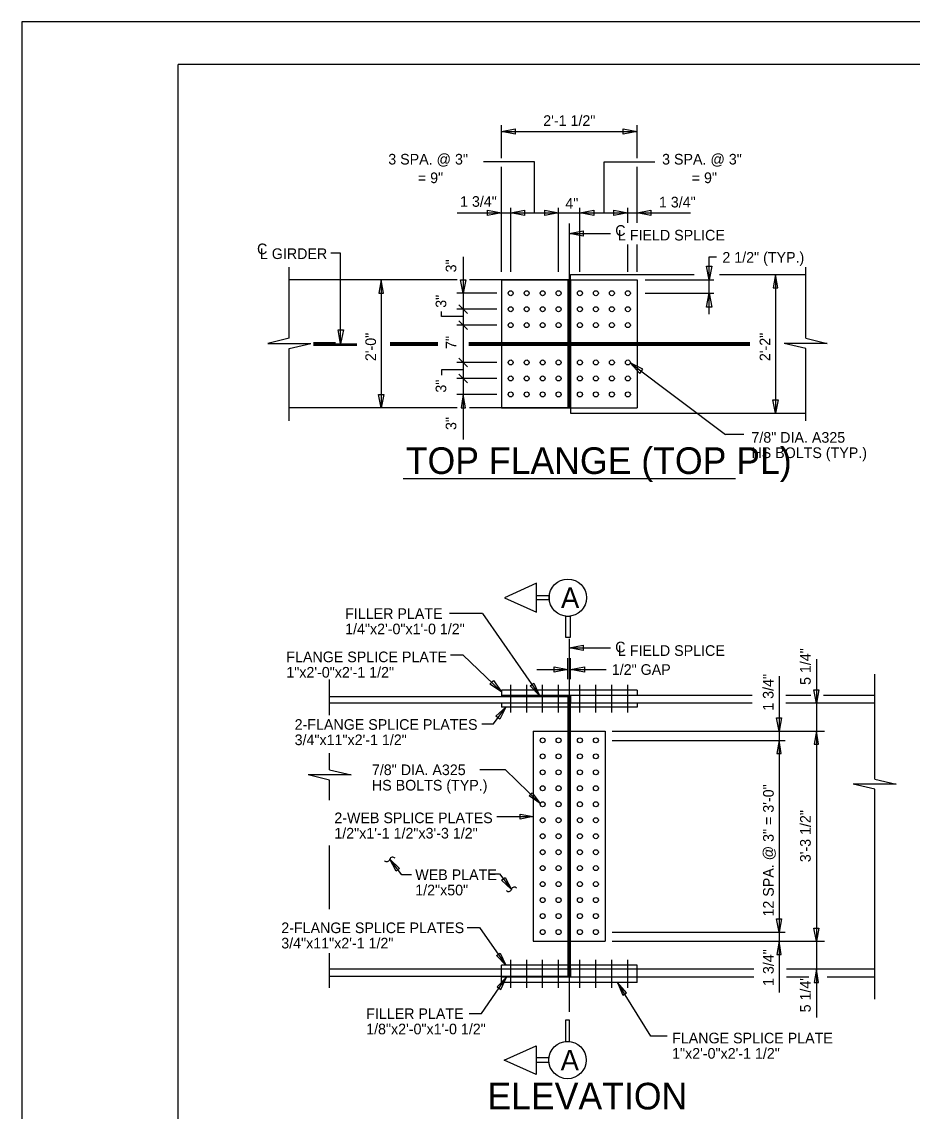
# Model space of a CAD drawing. Extents: x -448.1 to -400, y -140.7 to -111.4.
# Drawn here: x -448.13 to -434.2, y -128.41 to -111.36 of the extents above; entities that cross this region are included whole.
import ezdxf

# ---------------------------------------------------------------- set-up
doc = ezdxf.new("R2010")
doc.units = 0
for name, color, linetype in [('BR_AUTO DIMENSION', 7, 'Continuous'), ('BR_BORDER LINES', 7, 'Continuous'), ('BR_CENTER LINES', 7, 'Continuous'), ('BR_STRUCTURAL STEEL', 7, 'Continuous'), ('BR_TEXT', 7, 'Continuous'), ('Default', 7, 'Continuous'), ('Level 31', 7, 'Continuous')]:
    doc.layers.add(name, color=color, linetype=linetype)

msp = doc.modelspace()

# ---------------------------------------------------------------- linework, layer by layer
at = {"layer": 'BR_AUTO DIMENSION'}
for p, q in [((-440.631, -113.5), (-440.631, -112.984)), ((-438.506, -113.5), (-438.506, -112.984)), ((-440.631, -113.083), (-438.506, -113.083)), ((-440.631, -115.277), (-440.631, -113.636)), ((-438.506, -114.509), (-438.506, -113.636)), ((-441.321, -114.353), (-437.67, -114.353)), ((-440.485, -115.277), (-440.485, -114.278)), ((-439.735, -115.277), (-439.735, -114.278)), ((-439.402, -115.277), (-439.402, -114.278)), ((-438.652, -114.509), (-438.652, -114.278)), ((-438.652, -115.277), (-438.652, -114.85)), ((-438.506, -115.277), (-438.506, -114.85)), ((-443.145, -114.986), (-443.299, -114.986)), ((-443.145, -116.404), (-443.145, -114.986)), ((-441.228, -115.044), (-441.228, -117.899)), ((-437.38, -115.938), (-437.38, -115.042)), ((-437.38, -115.042), (-437.263, -115.042)), ((-442.511, -115.404), (-442.511, -117.404)), ((-438.382, -115.404), (-437.305, -115.404)), ((-436.343, -115.321), (-436.343, -117.487)), ((-440.704, -115.612), (-441.329, -115.612)), ((-438.382, -115.612), (-437.305, -115.612)), ((-440.704, -115.862), (-441.329, -115.862)), ((-441.161, -115.93), (-441.294, -115.795)), ((-441.161, -116.18), (-441.294, -116.045)), ((-440.704, -116.112), (-441.329, -116.112)), ((-440.704, -116.696), (-441.329, -116.696)), ((-441.161, -116.763), (-441.294, -116.628)), ((-438.614, -116.704), (-437.124, -117.825)), ((-440.704, -116.946), (-441.329, -116.946)), ((-441.161, -117.013), (-441.294, -116.878)), ((-440.704, -117.196), (-441.329, -117.196)), ((-436.838, -117.825), (-437.124, -117.825)), ((-440.926, -120.623), (-441.443, -120.623)), ((-440.926, -120.623), (-440.033, -121.906)), ((-441.428, -121.27), (-441.234, -121.27)), ((-441.234, -121.27), (-440.631, -121.848)), ((-439.59, -121.65), (-439.59, -121.323)), ((-439.548, -121.65), (-439.548, -121.323)), ((-435.703, -121.337), (-435.703, -126.945)), ((-435.703, -121.36), (-435.703, -122.255)), ((-440.076, -121.501), (-439.59, -121.501)), ((-439.548, -121.501), (-438.993, -121.501)), ((-436.286, -121.603), (-436.286, -126.554)), ((-440.756, -122.349), (-440.562, -122.089)), ((-440.939, -122.349), (-440.756, -122.349)), ((-438.9, -122.464), (-435.576, -122.464)), ((-438.9, -122.61), (-436.189, -122.61)), ((-440.969, -123.068), (-440.573, -123.068)), ((-440.023, -123.598), (-440.573, -123.068)), ((-440.702, -123.803), (-440.131, -123.803)), ((-442.19, -124.714), (-442.377, -124.472)), ((-442.036, -124.714), (-442.19, -124.714)), ((-440.814, -124.7), (-440.661, -124.7)), ((-440.661, -124.7), (-440.473, -124.942)), ((-441.165, -125.537), (-440.971, -125.537)), ((-440.971, -125.537), (-440.559, -126.13)), ((-438.9, -125.61), (-436.189, -125.61)), ((-438.9, -125.755), (-435.576, -125.755)), ((-440.942, -126.885), (-440.548, -126.318)), ((-438.295, -127.238), (-438.813, -126.401)), ((-441.136, -126.885), (-440.942, -126.885)), ((-438.038, -127.238), (-438.295, -127.238))]:
    msp.add_line(p, q, dxfattribs=at)
for points in [[(-440.415, -113.125), (-440.631, -113.083), (-440.415, -113.042)], [(-438.723, -113.042), (-438.506, -113.083), (-438.723, -113.125)], [(-440.848, -114.312), (-440.631, -114.353), (-440.848, -114.395)], [(-440.269, -114.395), (-440.485, -114.353), (-440.269, -114.312)], [(-439.952, -114.312), (-439.735, -114.353), (-439.952, -114.395)], [(-439.185, -114.395), (-439.402, -114.353), (-439.185, -114.312)], [(-438.869, -114.312), (-438.652, -114.353), (-438.869, -114.395)], [(-438.29, -114.395), (-438.506, -114.353), (-438.29, -114.312)], [(-439.352, -114.717), (-439.569, -114.676), (-439.352, -114.634)], [(-437.338, -115.187), (-437.38, -115.404), (-437.421, -115.187)], [(-442.546, -115.612), (-442.476, -115.612), (-442.511, -115.404)], [(-441.188, -115.404), (-441.228, -115.612), (-441.268, -115.404)], [(-436.378, -115.529), (-436.308, -115.529), (-436.343, -115.321)], [(-437.421, -115.829), (-437.38, -115.612), (-437.338, -115.829)], [(-443.103, -116.187), (-443.145, -116.404), (-443.186, -116.187)], [(-438.416, -116.801), (-438.614, -116.704), (-438.466, -116.868)], [(-442.471, -117.196), (-442.511, -117.404), (-442.551, -117.196)], [(-441.262, -117.404), (-441.193, -117.404), (-441.228, -117.196)], [(-436.303, -117.279), (-436.343, -117.487), (-436.383, -117.279)], [(-439.352, -121.203), (-439.569, -121.161), (-439.352, -121.119)], [(-439.806, -121.459), (-439.59, -121.501), (-439.806, -121.543)], [(-439.331, -121.543), (-439.548, -121.501), (-439.331, -121.459)], [(-440.754, -121.675), (-440.631, -121.848), (-440.809, -121.733)], [(-440.181, -121.755), (-440.124, -121.716), (-440.033, -121.906)], [(-435.663, -121.818), (-435.703, -122.026), (-435.743, -121.818)], [(-440.719, -122.232), (-440.562, -122.089), (-440.655, -122.279)], [(-436.246, -122.256), (-436.286, -122.464), (-436.326, -122.256)], [(-435.738, -122.672), (-435.668, -122.672), (-435.703, -122.464)], [(-436.321, -122.818), (-436.251, -122.818), (-436.286, -122.61)], [(-440.197, -123.479), (-440.149, -123.429), (-440.023, -123.598)], [(-440.339, -123.763), (-440.131, -123.803), (-440.339, -123.843)], [(-442.222, -124.616), (-442.277, -124.658), (-442.377, -124.472)], [(-440.629, -124.798), (-440.574, -124.756), (-440.473, -124.942)], [(-436.246, -125.402), (-436.286, -125.61), (-436.326, -125.402)], [(-435.663, -125.547), (-435.703, -125.755), (-435.743, -125.547)], [(-436.321, -125.964), (-436.251, -125.964), (-436.286, -125.755)], [(-440.706, -125.979), (-440.649, -125.94), (-440.559, -126.13)], [(-440.695, -126.469), (-440.638, -126.509), (-440.548, -126.318)], [(-435.738, -126.401), (-435.668, -126.401), (-435.703, -126.193)], [(-438.733, -126.597), (-438.674, -126.56), (-438.813, -126.401)]]:
    msp.add_lwpolyline(points, close=True, dxfattribs=at)
for points in [[(-440.113, -114.353), (-440.113, -113.557), (-440.91, -113.557)], [(-440.113, -114.353), (-440.113, -113.557), (-440.91, -113.557)], [(-439.024, -114.353), (-439.024, -113.557), (-438.228, -113.557)], [(-439.569, -114.676), (-438.921, -114.676)], [(-441.228, -115.979), (-441.565, -115.979), (-441.565, -115.897)], [(-441.228, -116.812), (-441.565, -116.812), (-441.565, -116.894)], [(-439.569, -121.161), (-438.921, -121.161)]]:
    msp.add_lwpolyline(points, dxfattribs=at)
at = {"layer": 'BR_BORDER LINES'}
for p in [(-400.801, -112.031), (-445.689, -140.031)]:
    msp.add_line(p, (-445.689, -112.031), dxfattribs=at)
at = {"layer": 'BR_CENTER LINES'}
for p, q in [((-439.569, -114.519), (-439.569, -117.404)), ((-443.568, -116.404), (-442.892, -116.404)), ((-442.371, -116.404), (-441.627, -116.404)), ((-441.142, -116.404), (-436.742, -116.404)), ((-439.569, -121.021), (-439.569, -126.859))]:
    msp.add_line(p, q, dxfattribs=at)
at = {"layer": 'BR_STRUCTURAL STEEL'}
for p, q in [((-441.323, -115.404), (-443.95, -115.404)), ((-439.548, -115.404), (-441.132, -115.404)), ((-440.631, -115.404), (-438.506, -115.404)), ((-440.631, -115.404), (-440.631, -117.404)), ((-439.59, -115.404), (-439.59, -117.404)), ((-439.548, -115.404), (-439.548, -115.321)), ((-439.548, -115.321), (-437.614, -115.321)), ((-439.548, -115.404), (-439.548, -117.404)), ((-438.506, -115.404), (-438.506, -117.404)), ((-437.22, -115.321), (-435.869, -115.321)), ((-443.568, -116.383), (-443.227, -116.383)), ((-443.568, -116.425), (-442.892, -116.425)), ((-442.371, -116.383), (-441.627, -116.383)), ((-442.371, -116.425), (-441.627, -116.425)), ((-441.142, -116.383), (-439.59, -116.383)), ((-441.142, -116.425), (-439.59, -116.425)), ((-439.548, -116.383), (-436.742, -116.383)), ((-439.548, -116.425), (-436.742, -116.425)), ((-441.323, -117.404), (-443.95, -117.404)), ((-439.59, -117.404), (-441.132, -117.404)), ((-440.631, -117.404), (-438.506, -117.404)), ((-439.548, -117.404), (-439.548, -117.487)), ((-439.548, -117.487), (-435.869, -117.487)), ((-440.631, -121.823), (-440.631, -121.906)), ((-438.506, -121.823), (-440.631, -121.823)), ((-440.485, -122.172), (-440.485, -121.74)), ((-440.485, -122.089), (-440.485, -121.823)), ((-440.235, -122.172), (-440.235, -121.74)), ((-439.985, -122.172), (-439.985, -121.74)), ((-439.735, -122.172), (-439.735, -121.74)), ((-439.402, -122.172), (-439.402, -121.74)), ((-439.152, -122.172), (-439.152, -121.74)), ((-438.902, -122.172), (-438.902, -121.74)), ((-438.652, -122.172), (-438.652, -121.74)), ((-438.506, -121.823), (-438.506, -121.906)), ((-439.59, -121.927), (-443.319, -121.927)), ((-436.708, -122.026), (-443.319, -122.026)), ((-440.631, -121.906), (-440.631, -121.927)), ((-438.506, -121.906), (-440.631, -121.906)), ((-440.631, -122.026), (-440.631, -122.089)), ((-438.944, -121.906), (-440.194, -121.906)), ((-439.59, -121.906), (-439.59, -121.927)), ((-439.59, -121.906), (-439.59, -122.026)), ((-439.59, -122.026), (-439.59, -126.193)), ((-439.548, -121.906), (-439.548, -122.026)), ((-436.708, -121.906), (-439.548, -121.906)), ((-439.548, -126.193), (-439.548, -122.026)), ((-438.506, -122.026), (-438.506, -122.089)), ((-435.79, -121.906), (-436.179, -121.906)), ((-434.789, -122.026), (-436.179, -122.026)), ((-434.789, -121.906), (-435.591, -121.906)), ((-438.506, -122.089), (-440.631, -122.089)), ((-440.131, -122.464), (-440.131, -125.755)), ((-440.131, -122.464), (-439.006, -122.464)), ((-439.006, -122.464), (-439.006, -125.755)), ((-440.131, -125.755), (-439.006, -125.755)), ((-440.631, -126.401), (-440.631, -126.13)), ((-438.506, -126.13), (-440.631, -126.13)), ((-440.485, -126.485), (-440.485, -126.047)), ((-440.235, -126.485), (-440.235, -126.047)), ((-439.985, -126.485), (-439.985, -126.047)), ((-439.735, -126.485), (-439.735, -126.047)), ((-439.402, -126.485), (-439.402, -126.047)), ((-439.152, -126.485), (-439.152, -126.047)), ((-438.902, -126.485), (-438.902, -126.047)), ((-438.652, -126.485), (-438.652, -126.047)), ((-438.506, -126.401), (-438.506, -126.13)), ((-436.682, -126.193), (-443.319, -126.193)), ((-439.59, -126.308), (-443.319, -126.308)), ((-438.506, -126.318), (-440.631, -126.318)), ((-439.59, -126.193), (-439.59, -126.318)), ((-439.548, -126.193), (-439.548, -126.318)), ((-436.682, -126.318), (-439.548, -126.318)), ((-434.789, -126.193), (-436.17, -126.193)), ((-435.823, -126.318), (-436.17, -126.318)), ((-434.789, -126.318), (-435.535, -126.318)), ((-438.506, -126.401), (-440.631, -126.401))]:
    msp.add_line(p, q, dxfattribs=at)
for centre in [(-440.485, -115.612), (-440.485, -115.612), (-440.235, -115.612), (-440.235, -115.612), (-439.985, -115.612), (-439.985, -115.612), (-439.735, -115.612), (-439.735, -115.612), (-439.402, -115.612), (-439.402, -115.612), (-439.152, -115.612), (-439.152, -115.612), (-438.902, -115.612), (-438.902, -115.612), (-438.652, -115.612), (-438.652, -115.612), (-440.485, -115.862), (-440.485, -115.862), (-440.235, -115.862), (-440.235, -115.862), (-439.985, -115.862), (-439.985, -115.862), (-439.735, -115.862), (-439.735, -115.862), (-439.402, -115.862), (-439.402, -115.862), (-439.152, -115.862), (-439.152, -115.862), (-438.902, -115.862), (-438.902, -115.862), (-438.652, -115.862), (-438.652, -115.862), (-440.485, -116.112), (-440.485, -116.112), (-440.235, -116.112), (-440.235, -116.112), (-439.985, -116.112), (-439.985, -116.112), (-439.735, -116.112), (-439.735, -116.112), (-439.402, -116.112), (-439.402, -116.112), (-439.152, -116.112), (-439.152, -116.112), (-438.902, -116.112), (-438.902, -116.112), (-438.652, -116.112), (-438.652, -116.112), (-440.485, -116.696), (-440.485, -116.696), (-440.235, -116.696), (-440.235, -116.696), (-439.985, -116.696), (-439.985, -116.696), (-439.735, -116.696), (-439.735, -116.696), (-439.402, -116.696), (-439.402, -116.696), (-439.152, -116.696), (-439.152, -116.696), (-438.902, -116.696), (-438.902, -116.696), (-438.652, -116.696), (-438.652, -116.696), (-440.485, -116.946), (-440.485, -116.946), (-440.235, -116.946), (-440.235, -116.946), (-439.985, -116.946), (-439.985, -116.946), (-439.735, -116.946), (-439.735, -116.946), (-439.402, -116.946), (-439.402, -116.946), (-439.152, -116.946), (-439.152, -116.946), (-438.902, -116.946), (-438.902, -116.946), (-438.652, -116.946), (-438.652, -116.946), (-440.485, -117.196), (-440.485, -117.196), (-440.235, -117.196), (-440.235, -117.196), (-439.985, -117.196), (-439.985, -117.196), (-439.735, -117.196), (-439.735, -117.196), (-439.402, -117.196), (-439.402, -117.196), (-439.152, -117.196), (-439.152, -117.196), (-438.902, -117.196), (-438.902, -117.196), (-438.652, -117.196), (-438.652, -117.196), (-439.985, -122.61), (-439.985, -122.61), (-439.735, -122.61), (-439.735, -122.61), (-439.402, -122.61), (-439.402, -122.61), (-439.152, -122.61), (-439.152, -122.61), (-439.985, -122.86), (-439.985, -122.86), (-439.735, -122.86), (-439.735, -122.86), (-439.402, -122.86), (-439.402, -122.86), (-439.152, -122.86), (-439.152, -122.86), (-439.985, -123.11), (-439.985, -123.11), (-439.735, -123.11), (-439.735, -123.11), (-439.402, -123.11), (-439.402, -123.11), (-439.152, -123.11), (-439.152, -123.11), (-439.985, -123.36), (-439.985, -123.36), (-439.735, -123.36), (-439.735, -123.36), (-439.402, -123.36), (-439.402, -123.36), (-439.152, -123.36), (-439.152, -123.36), (-439.985, -123.61), (-439.985, -123.61), (-439.735, -123.61), (-439.735, -123.61), (-439.402, -123.61), (-439.402, -123.61), (-439.152, -123.61), (-439.152, -123.61), (-439.985, -123.86), (-439.985, -123.86), (-439.735, -123.86), (-439.735, -123.86), (-439.402, -123.86), (-439.402, -123.86), (-439.152, -123.86), (-439.152, -123.86), (-439.985, -124.11), (-439.985, -124.11), (-439.735, -124.11), (-439.735, -124.11), (-439.402, -124.11), (-439.402, -124.11), (-439.152, -124.11), (-439.152, -124.11), (-439.985, -124.36), (-439.985, -124.36), (-439.735, -124.36), (-439.735, -124.36), (-439.402, -124.36), (-439.402, -124.36), (-439.152, -124.36), (-439.152, -124.36), (-439.985, -124.61), (-439.985, -124.61), (-439.735, -124.61), (-439.735, -124.61), (-439.402, -124.61), (-439.402, -124.61), (-439.152, -124.61), (-439.152, -124.61), (-439.985, -124.86), (-439.985, -124.86), (-439.735, -124.86), (-439.735, -124.86), (-439.402, -124.86), (-439.402, -124.86), (-439.152, -124.86), (-439.152, -124.86), (-439.985, -125.11), (-439.985, -125.11), (-439.735, -125.11), (-439.735, -125.11), (-439.402, -125.11), (-439.402, -125.11), (-439.152, -125.11), (-439.152, -125.11), (-439.985, -125.36), (-439.985, -125.36), (-439.735, -125.36), (-439.735, -125.36), (-439.402, -125.36), (-439.402, -125.36), (-439.152, -125.36), (-439.152, -125.36), (-439.985, -125.61), (-439.985, -125.61), (-439.735, -125.61), (-439.735, -125.61), (-439.402, -125.61), (-439.402, -125.61), (-439.152, -125.61), (-439.152, -125.61)]:
    msp.add_circle(centre, 0.0391, dxfattribs=at)
at = {"layer": 'BR_TEXT'}
msp.add_line((-442.168, -118.514), (-436.969, -118.514), dxfattribs=at)
for points in [[(-440.083, -120.151), (-440.583, -120.377), (-440.083, -120.602)], [(-439.882, -120.41), (-440.083, -120.41), (-440.083, -120.343), (-439.882, -120.343)], [(-439.557, -121.002), (-439.624, -121.002), (-439.624, -120.668), (-439.557, -120.668)], [(-439.563, -126.989), (-439.629, -126.989), (-439.629, -127.322), (-439.563, -127.322)], [(-440.088, -127.839), (-440.588, -127.614), (-440.088, -127.389)], [(-439.888, -127.581), (-440.088, -127.581), (-440.088, -127.648), (-439.888, -127.648)]]:
    msp.add_lwpolyline(points, close=True, dxfattribs=at)
for centre in [(-439.591, -120.377), (-439.596, -127.614)]:
    msp.add_circle(centre, 0.292, dxfattribs=at)
at = {"layer": 'Default'}
for p, q in [((-443.95, -116.316), (-443.95, -115.207)), ((-435.869, -116.316), (-435.869, -115.207)), ((-435.869, -116.316), (-435.869, -115.207)), ((-443.95, -116.316), (-444.285, -116.397)), ((-444.285, -116.397), (-443.614, -116.397)), ((-443.95, -116.477), (-443.614, -116.397)), ((-435.534, -116.397), (-436.205, -116.397)), ((-435.869, -116.477), (-436.205, -116.397)), ((-435.534, -116.397), (-436.205, -116.397)), ((-435.869, -116.477), (-436.205, -116.397)), ((-435.869, -116.316), (-435.534, -116.397)), ((-435.869, -116.316), (-435.534, -116.397)), ((-443.95, -117.607), (-443.95, -116.477)), ((-435.869, -117.607), (-435.869, -116.477)), ((-435.869, -117.607), (-435.869, -116.477)), ((-443.319, -122.216), (-443.319, -121.659)), ((-434.789, -123.215), (-434.789, -121.572)), ((-443.319, -123.071), (-443.319, -122.808)), ((-443.319, -123.071), (-442.983, -123.151)), ((-442.983, -123.151), (-443.655, -123.151)), ((-443.319, -123.232), (-443.655, -123.151)), ((-443.319, -123.546), (-443.319, -123.232)), ((-434.789, -123.215), (-434.454, -123.296)), ((-434.454, -123.296), (-435.125, -123.296)), ((-434.789, -123.376), (-435.125, -123.296)), ((-434.789, -126.662), (-434.789, -123.376)), ((-443.319, -125.254), (-443.319, -124.256)), ((-443.319, -126.481), (-443.319, -125.942))]:
    msp.add_line(p, q, dxfattribs=at)
for centre, start, end in [((-442.331, -124.487), 39.9477, 162.4119), ((-442.424, -124.458), 219.9477, 342.4119), ((-440.52, -124.927), 219.9477, 342.4119), ((-440.427, -124.956), 39.9477, 162.4119)]:
    msp.add_arc(centre, 0.0488, start, end, dxfattribs=at)
at = {"layer": 'Level 31'}
msp.add_lwpolyline([(-448.133, -140.698), (-400.133, -140.698), (-400.133, -111.364), (-448.133, -111.364)], close=True, dxfattribs=at)

# ---------------------------------------------------------------- texts
at = {"layer": 'BR_TEXT'}
for s, height, p in [('2\'-1 1/2"', 0.1667, (-439.976, -112.994)), ('3 SPA. @ 3" ', 0.16667, (-442.4, -113.598)), ('3 SPA. @ 3" ', 0.16667, (-438.116, -113.598)), ('= 9"', 0.1667, (-441.937, -113.889)), ('= 9"', 0.1667, (-437.653, -113.889)), ('1 3/4"', 0.1667, (-441.277, -114.26)), ('4"', 0.1667, (-439.63, -114.29)), ('1 3/4"', 0.1667, (-438.166, -114.27)), ('C', 0.167, (-438.849, -114.714)), ('L FIELD SPLICE', 0.16667, (-438.807, -114.787)), ('C', 0.167, (-444.453, -115.002)), ('L GIRDER', 0.1667, (-444.408, -115.077)), ('2 1/2" (TYP.)', 0.16667, (-437.173, -115.134)), ('7/8" DIA. A325', 0.16667, (-436.719, -117.952)), ('TOP FLANGE (TOP PL)', 0.41667, (-442.126, -118.441)), ('HS BOLTS (TYP.)', 0.16667, (-436.719, -118.192)), ('A', 0.32, (-439.698, -120.537)), ('FILLER PLATE', 0.16667, (-443.075, -120.71)), ('1/4"x2\'-0"x1\'-0 1/2"', 0.16667, (-443.075, -120.95)), ('FLANGE SPLICE PLATE', 0.16667, (-443.995, -121.387)), ('C', 0.167, (-438.85, -121.233)), ('L FIELD SPLICE', 0.16667, (-438.807, -121.288)), ('1"x2\'-0"x2\'-1 1/2"', 0.16667, (-443.995, -121.628)), ('1/2" GAP', 0.1667, (-438.903, -121.585)), ('2-FLANGE SPLICE PLATES', 0.16667, (-443.865, -122.445)), ('3/4"x11"x2\'-1 1/2"', 0.16667, (-443.865, -122.685)), ('7/8" DIA. A325', 0.16667, (-442.656, -123.154)), ('HS BOLTS (TYP.)', 0.16667, (-442.656, -123.395)), ('2-WEB SPLICE PLATES', 0.16667, (-443.244, -123.906)), ('1/2"x1\'-1 1/2"x3\'-3 1/2"', 0.16667, (-443.244, -124.146)), ('WEB PLATE', 0.1667, (-441.978, -124.796)), ('1/2"x50"', 0.1667, (-441.978, -125.036)), ('2-FLANGE SPLICE PLATES', 0.16667, (-444.074, -125.627)), ('3/4"x11"x2\'-1 1/2"', 0.16667, (-444.074, -125.867)), ('FILLER PLATE', 0.16667, (-442.746, -126.971)), ('1/8"x2\'-0"x1\'-0 1/2"', 0.16667, (-442.746, -127.211)), ('FLANGE SPLICE PLATE', 0.16667, (-437.96, -127.352)), ('A', 0.32, (-439.703, -127.774)), ('1"x2\'-0"x2\'-1 1/2"', 0.16667, (-437.96, -127.592)), ('ELEVATION', 0.4167, (-440.85, -128.386))]:
    msp.add_text(s, height=height, dxfattribs=at).set_placement(p)
for s, height, p in [('3"', 0.1667, (-441.335, -115.286)), ('3"', 0.1667, (-441.493, -115.84)), ('2\'-0"', 0.1667, (-442.592, -116.675)), ('2\'-2"', 0.1667, (-436.424, -116.675)), ('7"', 0.1667, (-441.335, -116.484)), ('3"', 0.1667, (-441.493, -117.168)), ('3"', 0.1667, (-441.335, -117.753)), ('5 1/4"', 0.1667, (-435.791, -121.743)), ('1 3/4"', 0.1667, (-436.373, -122.146)), ('12 SPA. @ 3" = 3\'-0"', 0.16667, (-436.37, -125.367)), ('3\'-3 1/2"', 0.1667, (-435.791, -124.517)), ('1 3/4"', 0.1667, (-436.37, -126.454)), ('5 1/4"', 0.1667, (-435.791, -126.867))]:
    msp.add_text(s, height=height, rotation=90, dxfattribs=at).set_placement(p)

doc.saveas('drawing.dxf')
